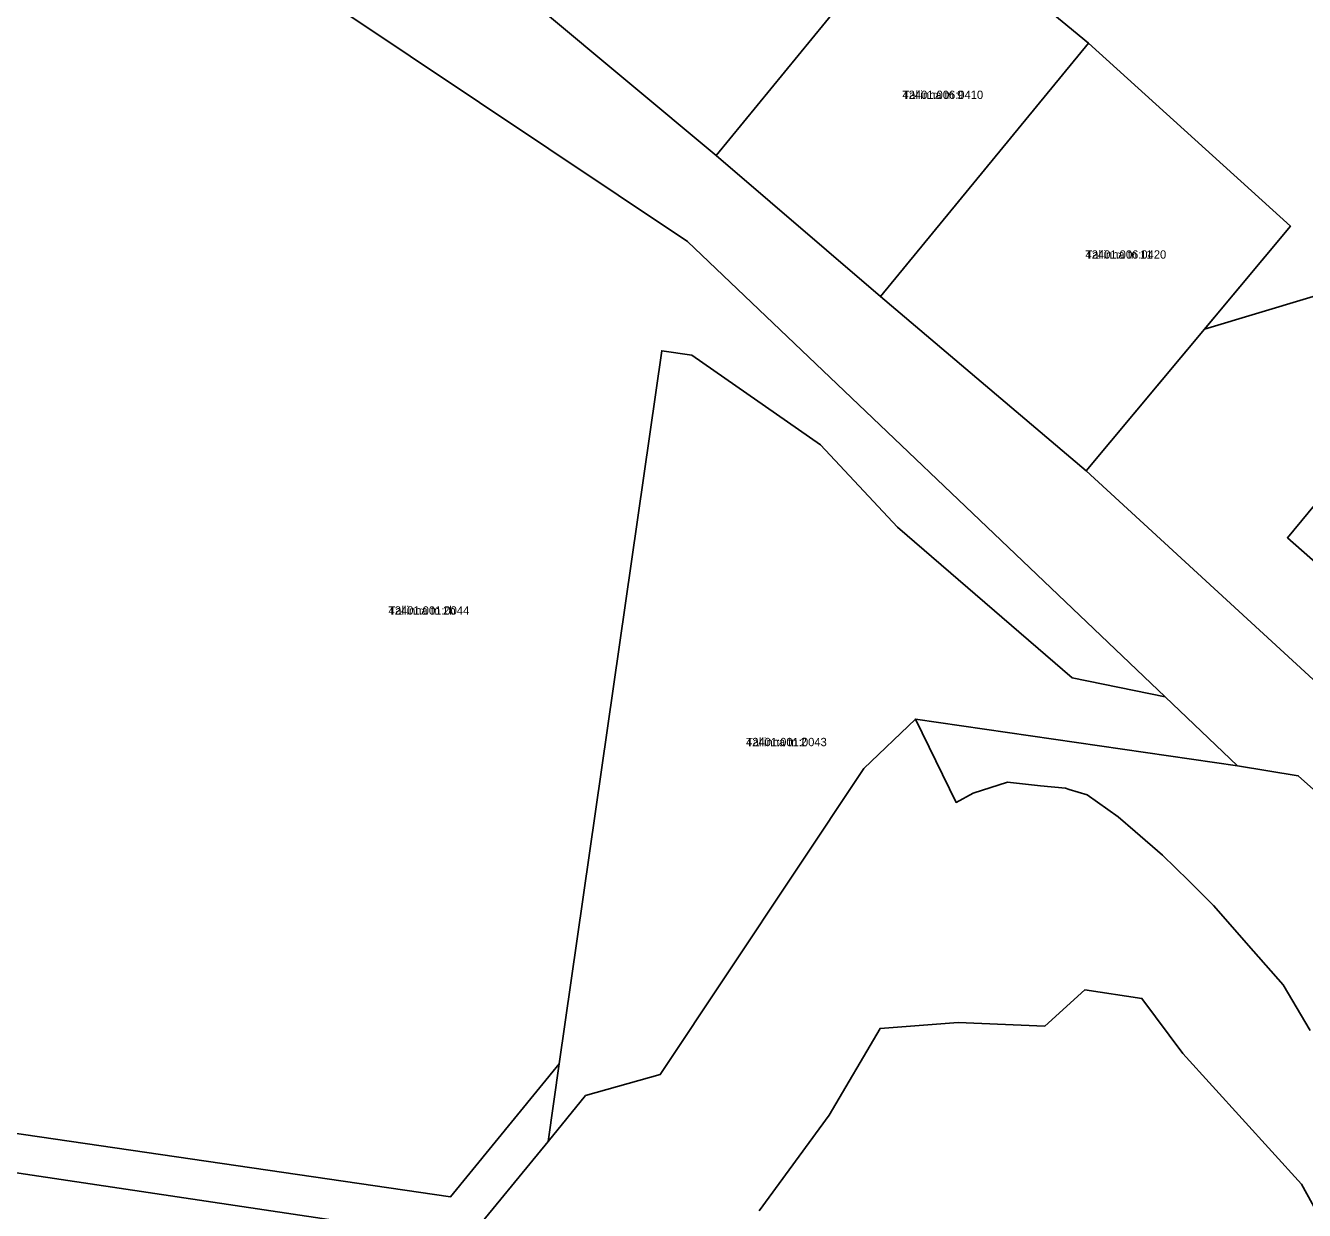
# Model space of a CAD drawing. Extents: x 595979 to 597983, y 6604231 to 6607350.
# Drawn here: x 596644 to 596873.6, y 6606340.2 to 6606552.8 of the extents above; entities that cross this region are included whole.
import ezdxf

# ---------------------------------------------------------------- set-up
doc = ezdxf.new("R2010")
doc.units = 0
for name, color, linetype in [('L_AADRESS', 7, 'Continuous'), ('PIIR', 7, 'Continuous'), ('TUNNUS', 7, 'Continuous')]:
    doc.layers.add(name, color=color, linetype=linetype)

msp = doc.modelspace()

# ---------------------------------------------------------------- linework, layer by layer
at = {"layer": 'PIIR'}
for points in [[(596909.1, 6606385.61), (596872.46, 6606418.2), (596861.56, 6606419.99), (596848.55, 6606432.38), (596762.79, 6606514.09), (596675.69, 6606572.34), (596638.27, 6606595.39), (596557.11, 6606645.51), (596555.44, 6606646.42), (596542.85, 6606653.57), (596526.52, 6606663), (596451.2, 6606705.15), (596442.76, 6606730.14), (596437.35, 6606745.96), (596437.73, 6606810.5), (596437.33, 6606810.61), (596437.96, 6606836.91), (596442.64, 6606872.04), (596470.43, 6606959.84)], [(596464.47, 6606887.4), (596457.38, 6606863.19), (596452.59, 6606835.16), (596451.96, 6606809.89), (596451.4, 6606745.94), (596455.33, 6606728.96), (596461.16, 6606718.64), (596465.96, 6606712.4), (596556.83, 6606658.51), (596558.45, 6606661.57), (596684.47, 6606582.41), (596720.93, 6606558.63), (596736.24, 6606555.98), (596767.98, 6606529.52), (596797.47, 6606504.22), (596834.39, 6606472.9), (596889.22, 6606422.58)], [(596902.6, 6606512.44), (596855.64, 6606498.37), (596871.06, 6606516.85), (596834.82, 6606549.67), (596804.78, 6606574.42), (596766.91, 6606605.63), (596790.45, 6606648.77), (596840.01, 6606619.43), (596912.39, 6606742.64), (596862.67, 6606771.48), (596925.85, 6606832.78)], [(596242.07, 6606528), (596367.46, 6606391.27), (596381.08, 6606376.31), (596448.58, 6606437.61), (596466.73, 6606447.57), (596477.99, 6606442.43), (596526.21, 6606427.77), (596552.3, 6606423.95), (596569.63, 6606421.41), (596577.86, 6606420.2), (596577.35, 6606416.75), (596569.74, 6606364.59), (596720.28, 6606342.66), (596739.8, 6606366.49), (596737.8, 6606352.55), (596723.23, 6606334.88), (596484.87, 6606370.45), (596472.89, 6606367.48), (596450.64, 6606352.84), (596418.86, 6606327.05)], [(596889.22, 6606422.58), (596834.39, 6606472.9), (596855.64, 6606498.37), (596902.6, 6606512.44)], [(596880.53, 6606472.99), (596870.54, 6606460.92), (596894.03, 6606440.25)], [(596484.87, 6606370.45), (596723.23, 6606334.88), (596737.8, 6606352.55), (596744.51, 6606360.8), (596757.92, 6606364.6), (596794.47, 6606419.52), (596803.74, 6606428.37), (596811.04, 6606413.41), (596814.09, 6606415.07), (596820.28, 6606417.04), (596826.18, 6606416.41), (596830.71, 6606415.97), (596831.37, 6606415.77), (596834.59, 6606414.78), (596840.15, 6606410.82), (596843.21, 6606408.18), (596848.1, 6606403.95), (596852.78, 6606399.4), (596854.5, 6606397.68), (596857.24, 6606394.94), (596864.44, 6606386.7), (596869.78, 6606380.71), (596874.63, 6606372.52)], [(596874.63, 6606372.52), (596869.78, 6606380.71), (596864.44, 6606386.7), (596857.24, 6606394.94), (596854.5, 6606397.68), (596852.78, 6606399.4), (596848.1, 6606403.95), (596843.21, 6606408.18), (596840.15, 6606410.82), (596834.59, 6606414.78), (596831.37, 6606415.77), (596830.71, 6606415.97), (596826.18, 6606416.41), (596820.28, 6606417.04), (596814.09, 6606415.07), (596811.04, 6606413.41), (596803.74, 6606428.37), (596861.56, 6606419.99), (596872.46, 6606418.2), (596909.1, 6606385.61)], [(596775.7, 6606340.13), (596788.28, 6606357.27), (596797.4, 6606372.86), (596811.43, 6606373.94), (596826.98, 6606373.3), (596834.18, 6606379.78), (596844.41, 6606378.25), (596851.76, 6606368.35), (596873.07, 6606344.89), (596880.13, 6606332.1)], [(596880.13, 6606332.1), (596873.07, 6606344.89), (596851.76, 6606368.35), (596844.41, 6606378.25), (596834.18, 6606379.78), (596826.98, 6606373.3), (596811.43, 6606373.94), (596797.4, 6606372.86), (596788.28, 6606357.27), (596775.7, 6606340.13)]]:
    msp.add_lwpolyline(points, dxfattribs=at)
for points in [[(596736.24, 6606555.98), (596766.91, 6606605.63), (596804.78, 6606574.42), (596767.98, 6606529.52)], [(596634.48, 6606573.71), (596638.27, 6606595.39), (596675.69, 6606572.34), (596762.79, 6606514.09), (596848.55, 6606432.38), (596831.88, 6606435.78), (596800.52, 6606462.81), (596786.69, 6606477.58), (596763.58, 6606493.7), (596758.19, 6606494.47), (596739.8, 6606366.49), (596720.28, 6606342.66), (596569.74, 6606364.59), (596577.35, 6606416.75), (596577.86, 6606420.2), (596578.99, 6606421.05), (596609.49, 6606416.58), (596622.09, 6606502.86), (596630.11, 6606548.73)], [(596767.98, 6606529.52), (596804.78, 6606574.42), (596834.82, 6606549.67), (596797.47, 6606504.22)], [(596871.06, 6606516.85), (596834.39, 6606472.9), (596797.47, 6606504.22), (596834.82, 6606549.67)], [(596739.8, 6606366.49), (596758.19, 6606494.47), (596763.58, 6606493.7), (596786.69, 6606477.58), (596800.52, 6606462.81), (596831.88, 6606435.78), (596848.55, 6606432.38), (596861.56, 6606419.99), (596803.74, 6606428.37), (596794.47, 6606419.52), (596757.92, 6606364.6), (596744.51, 6606360.8), (596737.8, 6606352.55)], [(596880.53, 6606472.99), (596893.16, 6606463.53), (596901.5, 6606457.46), (596913.52, 6606464.07), (596922.57, 6606456.35), (596901.72, 6606435.27), (596897.91, 6606434.49), (596894.03, 6606440.25), (596870.54, 6606460.92)]]:
    msp.add_lwpolyline(points, close=True, dxfattribs=at)

# ---------------------------------------------------------------- texts
at = {"layer": 'L_AADRESS'}
for s, p in [('Tallinna tn 9', (596801.4, 6606539.65)), ('Tallinna tn 11', (596834.27, 6606511)), ('Tallinna tn 2b', (596709.14, 6606447.12)), ('Tallinna tn 2', (596773.32, 6606423.51))]:
    msp.add_text(s, height=1.5, dxfattribs=at).set_placement(p)
at = {"layer": 'TUNNUS'}
for s, p in [('42401:006:0410', (596801.4, 6606539.65)), ('42401:006:0420', (596834.27, 6606511)), ('42401:001:0044', (596709.14, 6606447.12)), ('42401:001:0043', (596773.32, 6606423.51))]:
    msp.add_text(s, height=1.5, dxfattribs=at).set_placement(p)

doc.saveas('drawing.dxf')
